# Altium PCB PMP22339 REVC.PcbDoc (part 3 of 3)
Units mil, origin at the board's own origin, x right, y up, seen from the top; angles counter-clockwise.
Board outline 4555 x 3750 mil, 4 copper layers (Top Layer, Signal Layer 2, Signal Layer 3, Bottom Layer), stack 62.6 mil thick; 180 components, 83 nets, 384 pads, 132 vias.
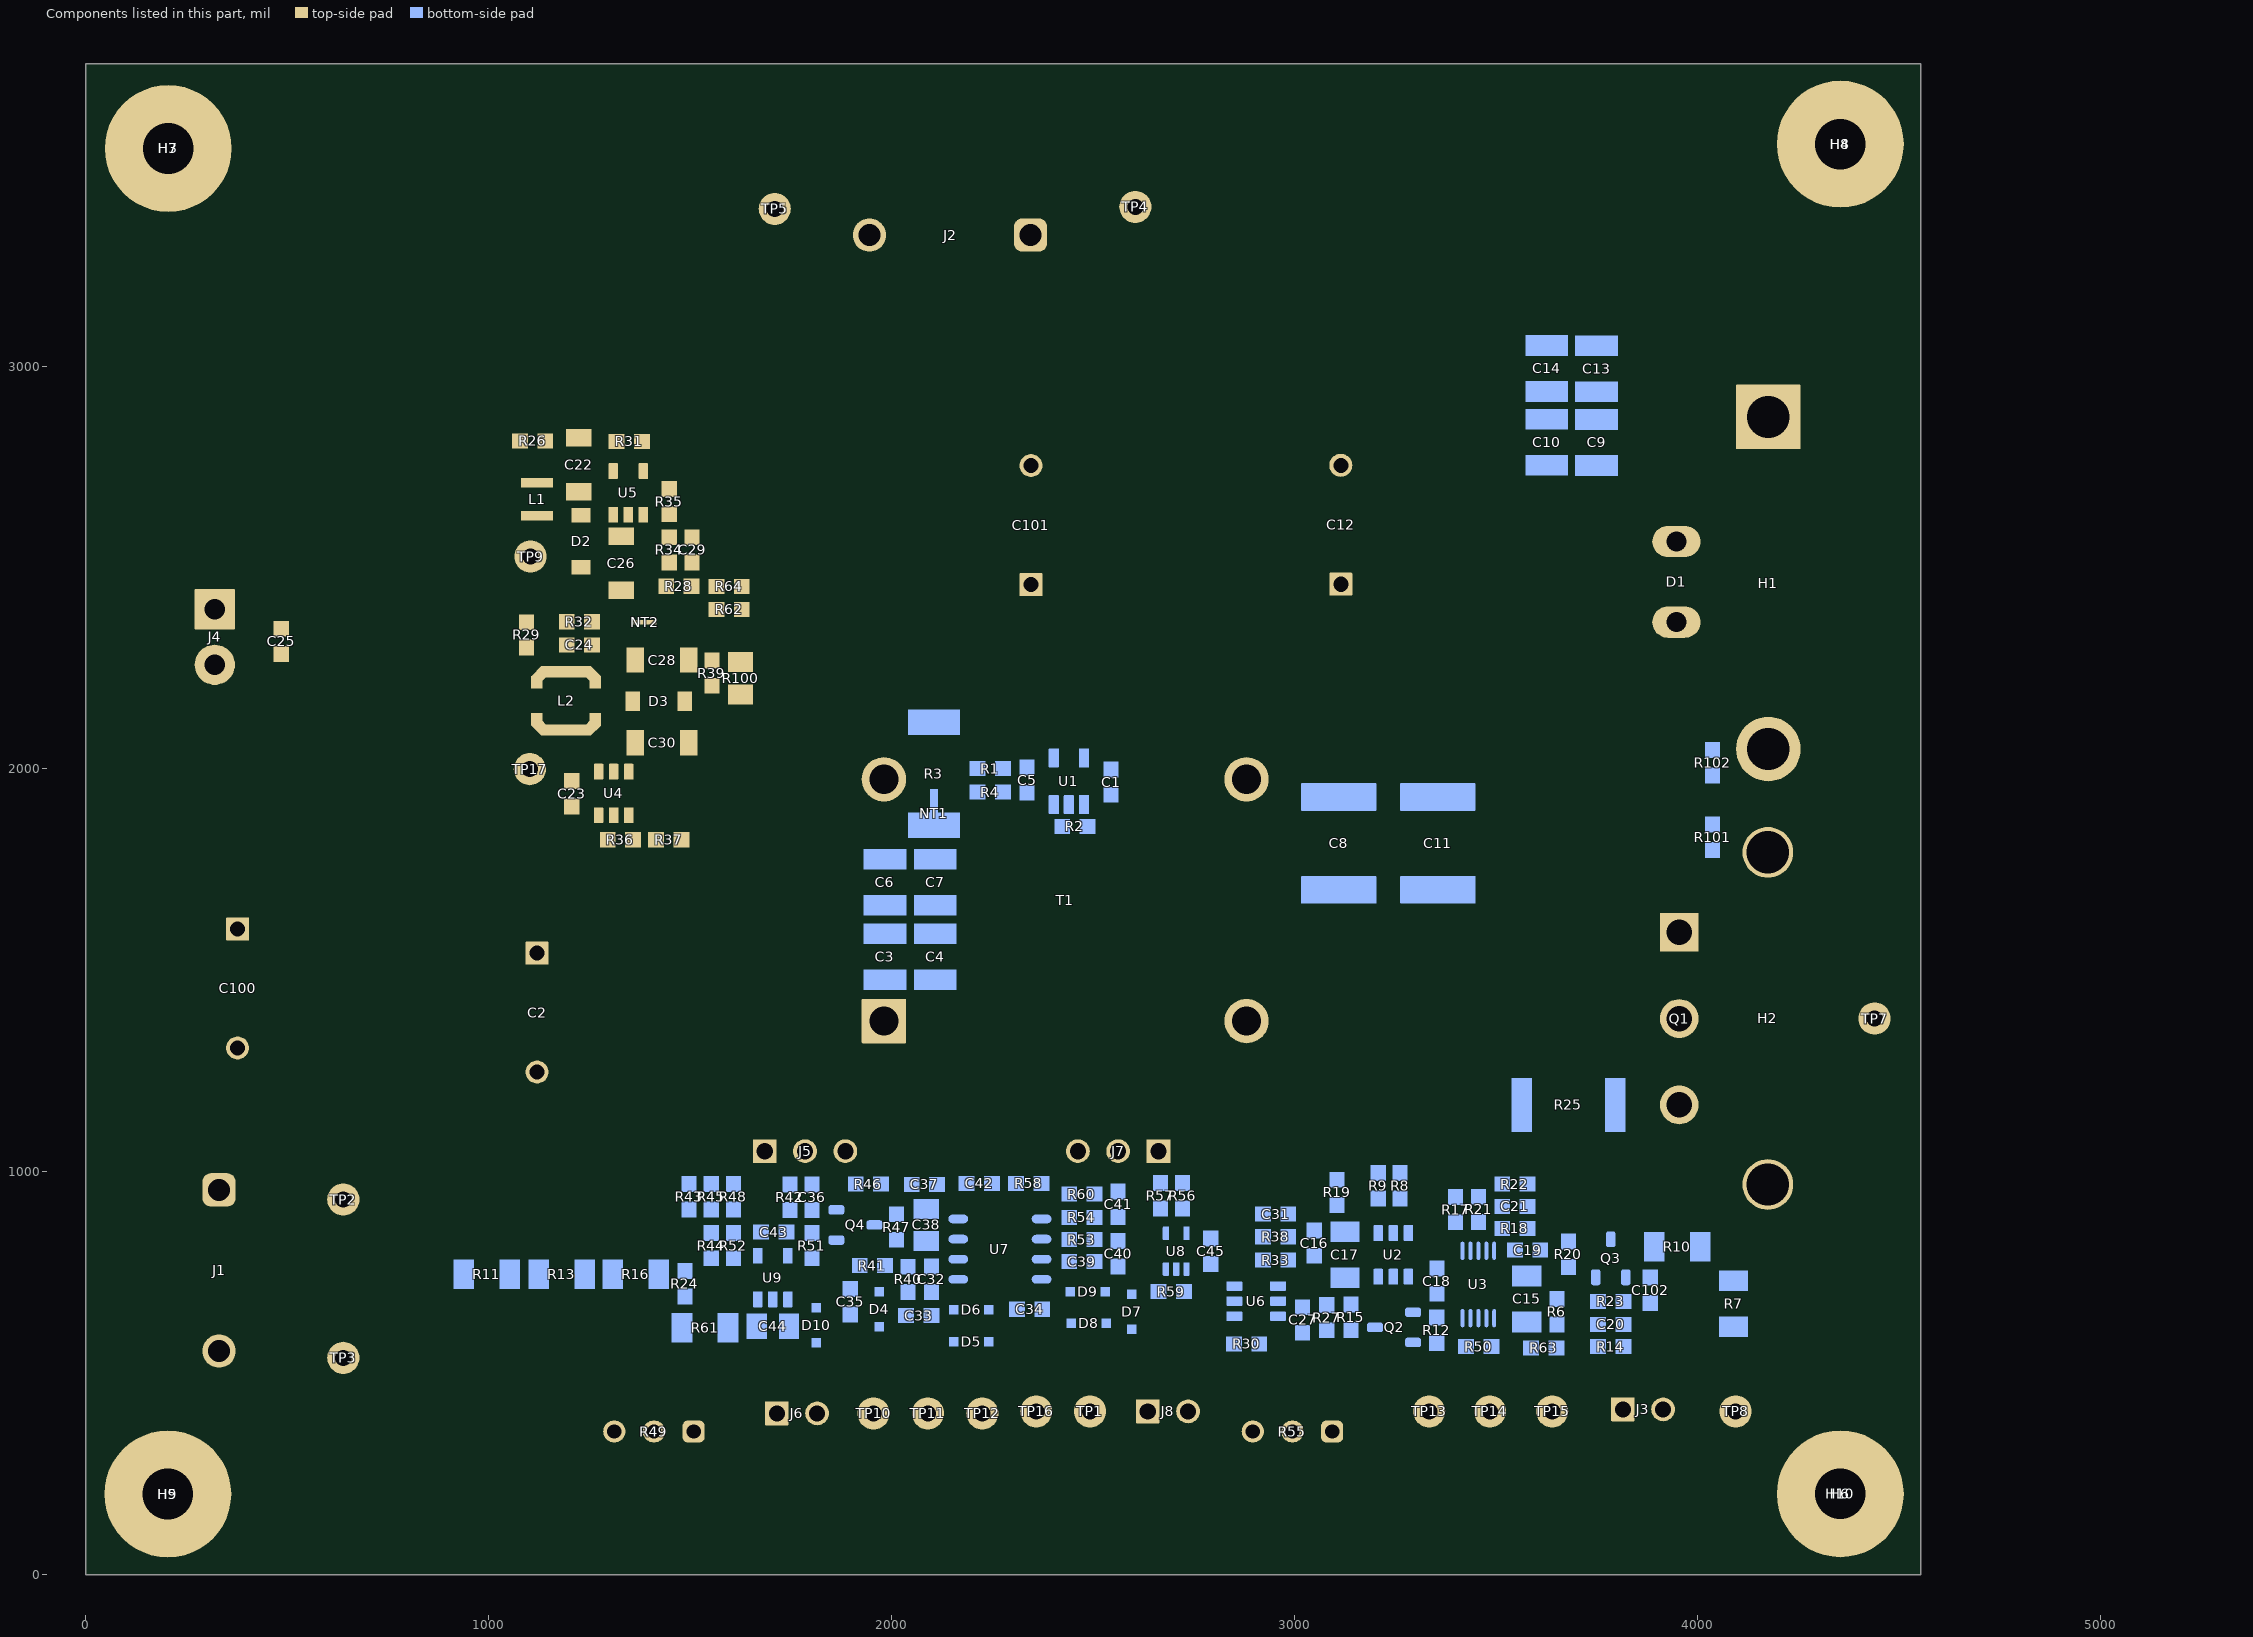
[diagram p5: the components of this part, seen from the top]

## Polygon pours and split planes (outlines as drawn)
VOUT on Bottom Layer "BOTTOM_LAYER_VOUT_P088" (solid, remove dead copper, pour order 88): 4042.91,2488.6 3318.01,2488.6 3226.61,2580 2276.8,2580 2160,2696.8 2160,3405 2250,3495 2440,3495 2520,3415 2520,2941.76 2561.76,2900 3472,2900 3565,2807 4038,2807 4050.01,2794.99 4050.01,2495.64
NetC8_2 on Bottom Layer "BOTTOM_LAYER_NETC8_2_P089" (solid, remove dead copper, pour order 89): 2775.5,1928.5 2836,1868 2836,1867 3704.57,1867 4064.88,2227.3 4064.88,2440 3318.01,2440 3230.66,2352.65 2833.65,2352.65 2776,2295
NetQ1_3 on Bottom Layer "BOTTOM_LAYER_NETQ1_3_P090" (solid, remove dead copper, pour order 90): 3770,1231.72 3983.28,1231.72 4015,1200 4015,1135.54 3979.46,1100 3770.17,1100 3770,1099.83
NetC8_1 on Bottom Layer "BOTTOM_LAYER_NETC8_1_P091" (solid, remove dead copper, pour order 91): 2814,1273 2776,1311 2776,1724 2837,1785 3706,1785 3825,1666 3825,1534.34 3891.34,1468 4477,1468 4517,1428 4517,1337 4472,1292 3261,1292 3242,1273
NetR1_1 on Bottom Layer "BOTTOM_LAYER_NETR1_1_P093" (solid, remove dead copper, pour order 93): 2235,2082.2 2235,2161.3 2188.88,2207.42 1947.42,2207.42 1904,2164 1904,1961.12 1935.12,1930 2010.16,1930 2040.16,1960 2040.16,2025.16 2058.05,2043.05 2195.84,2043.05
VIN on Bottom Layer "BOTTOM_LAYER_VIN_P094" (solid, remove dead copper, pour order 94): 1916,1514 1878,1476 1878,1303 1895,1286 2186.87,1286 2204.51,1303.64 2204.51,1472.06 2161.57,1515
-5V on Bottom Layer "BOTTOM_LAYER_-5V_P128" (solid, remove dead copper, pour order 128): 3214.7,849.62 3214.7,831.58 3224.71,821.56 3301.76,821.56 3302.32,822.12 3308.48,815.96 3308.48,771.29 3301.83,764.64 3190.83,764.64 3165,790.48 3165,849.31
GND on Bottom Layer "BOTTOM_LAYER_GND_P148" (solid, remove dead copper, pour order 148): 25.49,25.49 25.49,3724.51 4529.51,3724.51 4529.51,25.49
NetC9_2 on Bottom Layer "BOTTOM_LAYER_NETC9_2_P142" (solid, remove dead copper, pour order 142): 3697,2960.97 3697.03,2961 3803.27,2961 3803.27,2843 3696.97,2843
NetC10_2 on Bottom Layer "BOTTOM_LAYER_NETC10_2_P140" (solid, remove dead copper, pour order 140): 3573,2843 3573,2960.97 3572.97,2961 3573.97,2962 3678,2962 3678,2844 3679,2843
VOUT on Bottom Layer "BOTTOM_LAYER_VOUT_P138" (solid, remove dead copper, pour order 138): 4425,2857.42
NetC4_2 on Bottom Layer "BOTTOM_LAYER_NETC4_2_P136" (solid, remove dead copper, pour order 136): 2256,1674
NetC4_2 on Bottom Layer "BOTTOM_LAYER_NETC4_2_P134" (solid, remove dead copper, pour order 134): 2055,1687 2055,1566 2161.57,1566 2161.57,1686
NetC3_2 on Bottom Layer "BOTTOM_LAYER_NETC3_2_P130" (solid, remove dead copper, pour order 130): 1929,1690 2035.57,1690 2036.57,1689 2036.57,1564 1929,1564
-5V on Bottom Layer "BOTTOM_LAYER_-5V_P127" (solid, remove dead copper, pour order 127): 3040,545.6
-5V on Bottom Layer "BOTTOM_LAYER_-5V_P126" (solid, remove dead copper, pour order 126): 2971,728 2970.52,727.52 2909.87,727.52 2872.35,690 2859,690 2859,667.63 2873.03,667.63 2881,659.66 2881,617.81 2893.64,605.18 2962.82,605.18 2990.98,577.02 3039,577.02 3039,603.74 3019.34,613.17 2980,652.5 2979.5,652 2937.66,652 2930,659.66 2931,660.66 2931,693.18 2942,704.17 2952,704.17
+18V on Bottom Layer "BOTTOM_LAYER_+18V_P121" (solid, remove dead copper, pour order 121): 2861,818
+18V on Bottom Layer "BOTTOM_LAYER_+18V_P120" (solid, remove dead copper, pour order 120): 3030.46,811 3020.62,801.16 2965.91,801 2965.12,801.79 2965.12,758.1 3022.22,701 3049,701 3093.54,656.46 3093.54,681.67 3120.87,709 3207,709 3221,723 3221,754.74 3213.58,762.16 3092.36,762.16 3079,775.52 3079,798 3066,811
-5V on Bottom Layer "BOTTOM_LAYER_-5V_P119" (solid, remove dead copper, pour order 119): 3218,865.4 3188.4,895 3174.52,908.88 3174.52,917.58 3151.65,940.45 2976.45,940.45 2965,929 2965,820 3086,820 3095,811 3095,784 3106,773 3207,773 3218,784.1
NetC24_2 on Bottom Layer "BOTTOM_LAYER_NETC24_2_P106" (solid, remove dead copper, pour order 106): 1330.12,2035 1330.12,2211.19 1216.3,2325 1132,2325 1121.97,2314.97 1121.97,2222.03 1231,2113 1231,2059.4 1265.4,2025 1320.33,2025
NetC15_1 on Bottom Layer "BOTTOM_LAYER_NETC15_1_P098" (solid, remove dead copper, pour order 98): 3558.12,581.18
NetC15_1 on Bottom Layer "BOTTOM_LAYER_NETC15_1_P097" (solid, remove dead copper, pour order 97): 3499.81,661.21 3490.81,652.21 3490.81,618.49 3507.12,602.18 3613.12,602.18 3613.12,652.33 3605.12,660.33
NetR1_1 on Top Layer "TOP_LAYER_NETR1_1_P092" (solid, remove dead copper, pour order 92): 1904,2164 1947.42,2207.42 2188.88,2207.42 2235,2161.3 2235,2080 2198.05,2043.05 2058.05,2043.05 2040.16,2025.16 2040.16,1960 2010.16,1930 1935.12,1930 1904,1961.12
VIN on Top Layer "TOP_LAYER_VIN_P095" (solid, remove dead copper, pour order 95): 224,935 225,936 225,1331 303,1409 1547,1409 1549,1411 1809,1411 1811,1409 1916,1514 2176,1514 2280,1410 2280,1217.94 2247.06,1185 900,1185 735,1020 735,895 665,825 290,825 225,890
no net on Top Layer "TOP_LAYER_NONET_P096" (solid, remove dead copper, pour order 96): 216,1108
GND on Top Layer "TOP_LAYER_GND_P152" (solid, remove dead copper, pour order 152): 25.49,25.49 25.49,3724.51 4529.51,3724.51 4529.51,25.49
NetR1_1 on Top Layer "TOP_LAYER_NETR1_1_P150" (solid, remove dead copper, pour order 150): 2015,2173
GND on Top Layer "TOP_LAYER_GND_P112" (solid, remove dead copper, pour order 112): 1564,2531
GND on Top Layer "TOP_LAYER_GND_P111" (solid, remove dead copper, pour order 111): 1297,2599 1298,2598 1406,2598 1418,2586 1418,2550 1410,2542 1304,2542 1297,2549
GND on Top Layer "TOP_LAYER_GND_P110" (solid, remove dead copper, pour order 110): 1569,2671
GND on Top Layer "TOP_LAYER_GND_P108" (solid, remove dead copper, pour order 108): 1467,2716 1418,2716 1407,2705 1251.02,2705 1249.02,2707 1192,2707 1172,2687 1040,2687 1043.08,2683.92 1043.08,2658 1464.84,2658 1466.84,2660
NetC28_2 on Top Layer "TOP_LAYER_NETC28_2_P105" (solid, remove dead copper, pour order 105): 1328,1965.18 1292.7,1965.18 1275.53,1948 1276,1947.53 1276,1927.42 1348.17,1855.25 1438.25,1855.25 1519,1936 1519,2301 1516,2304 1413.78,2304 1403.78,2294 1403.78,2189 1404,2031.4 1419.6,2015.8 1419.6,1978.6 1406,1965
GND on Top Layer "TOP_LAYER_GND_P104" (solid, remove dead copper, pour order 104): 1098,2256 1103,2261 1208.12,2261 1236,2288.88 1236,2326 1236.28,2326.28 1376.72,2326.28 1386,2317 1386,2228 1371,2213 1304,2213 1289,2198 1098,2198
NetC24_2 on Top Layer "TOP_LAYER_NETC24_2_P103" (solid, remove dead copper, pour order 103): 1301.61,1995.49 1299,1998.11 1299,2051.7 1342.75,2095.45 1342.75,2096.34 1385,2096.34 1385,2026.63 1380.94,2022.58 1338.58,2022.58 1325,2009 1325,1977.85 1318.54,1971.4 1301.61,1971.4
NetC23_1 on Top Layer "TOP_LAYER_NETC23_1_P102" (solid, remove dead copper, pour order 102): 1285,1979 1285,2059 1342.75,2116.75 1364.75,2116.75 1376,2128 1376,2180.19 1363.19,2193 1299,2193 1281,2175 1078,2175 1062,2159 1062,1974 1087,1949 1254.97,1949 1255.97,1948
NetC26_1 on Top Layer "TOP_LAYER_NETC26_1_P101" (solid, remove dead copper, pour order 101): 1459,2519 1445,2533 1218,2533 1203,2518 1203,2474.47 1256.47,2421 1446,2421 1459,2434
NetC22_1 on Top Layer "TOP_LAYER_NETC22_1_P100" (solid, remove dead copper, pour order 100): 1340,2837 1332,2845 1129.92,2845 1118,2833.08 1118,2799 1080.72,2761.72 1080.72,2730.25 1080.74,2696.8 1159.44,2696.8 1185.01,2722.37 1268.63,2722.37 1274,2717 1274.85,2717.85 1320.85,2717.85 1340,2737
NetD2_2 on Top Layer "TOP_LAYER_NETD2_2_P099" (solid, remove dead copper, pour order 99): 1317.34,2652.16 1316,2653.51 1090.51,2653.51 1056,2619 1056,2518 1087,2487 1124,2487 1188,2551 1253.34,2551 1312.34,2610 1317.34,2615
GND on Signal Layer 2 "SIGNAL_LAYER_2_GND_P144" (solid, remove dead copper, pour order 144): 0,0 0,6875 5140,6875 5140,0
GND on Signal Layer 3 "SIGNAL_LAYER_3_GND_P146" (solid, remove dead copper, pour order 146): 0,0 0,6875 5140,6875 5140,0

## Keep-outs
Keep-Out Layer:
  text ".Layer_Name" at 577,-858.49 h60

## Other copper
Top Layer:
  pour cut-out: 2645,1240 2646.42,1241.42 2646.42,1252.1 2296.45,1252.1 2289.34,1245 2291.51,1242.83 2291.51,1235 2648.7,1235
  pour cut-out: 3570.97,1039 3594.97,1015 3609.27,1015 3609.27,1007.1 3608.74,1006.58 3608.15,1007.18 3584.84,1007.18 3562.02,1030
  pour cut-out: 3599,1017.87 4118.2,1017.87 4106.91,1006.58 3593.74,1006.58
  pour cut-out: 3571.97,1038 3570.97,1039 3286.24,1039 3286.24,1034.02 3279.22,1027 3570.55,1027
  pour cut-out: 5263,1135
  pour cut-out: 2646.42,1252.1 2810.3,1088.23 3261.18,1088.23 3261.18,1074.02 3260.2,1075 2799,1075 2634,1240
  text ".Layer_Name" at 577,-858.49 h60
Signal Layer 2:
  pour cut-out: 2736.54,1260 2492.22,1260 2490.22,1262 2487.14,1258.92 2487.14,1242.71 2741.98,1242.71
  pour cut-out: 3261.18,1088.23 3079.77,1088.23 3063,1105 2895,1105 2738.16,1261.84 2726.37,1250.05 2888.19,1088.23 3053.77,1088.23 3070,1072 3249.12,1072
Bottom Layer:
  pour cut-out: 1346.39,801.59 1377.56,801.59 1384.63,808.66 1390.68,802.6 1390.68,688.88 1390.56,688.76 1345,688.76
  pour cut-out: 1160,801.59 1199.49,801.59 1200,801.08 1200,688.76 1161.24,688.76 1160,690
  pour cut-out: 975,801.59 1015,801.59 1015,688.76 976.52,688.76
  pour cut-out: 4033.58,690.5 4145.52,690.5 4147.5,692.48 4156.42,683.56 4156.42,660.94 4165,652.36 4165,642.82 4141.78,642.82 4134.59,650 4034.92,650 4033.84,651.09
  pour cut-out: 3930,756.86 3930,871.31 3969.73,871.31 3970,871.57 3970,757.19
  pour cut-out: 1908.61,1525 2182,1525 2182,1553.57 2171.57,1564 1908.61,1564
  pour cut-out: 2819,1792 2820,1793 3729.82,1793 3729.82,1861 2819,1861
  pour cut-out: 3611,931 3650,931 3712,869 3712,824.11 3718.11,824.11 3732,838 3732,876.37 3657.9,950.47 3610.77,950.47 3610.24,951
  pour cut-out: 3284.8,1055 3696.36,1055 3696.36,1045 3290.8,1045
  pour cut-out: 3185.12,1037.66 2991.34,1037.66 3013,1016 3013,1005 3174.91,1005 3178.07,1008.16
  text ".Layer_Name" at 577,-858.49 h60

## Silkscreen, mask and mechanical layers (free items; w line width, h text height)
Top Overlay:
  lines w8: 1221.81,1832.06 1250,1855.25 ; 1403.89,2741.04 1403.89,2741.32 1443.57,2781 ; 1586.01,2816 1486.01,2716 ; 1684,1133 1782,1133 ; 2564,1133 2662,1133 ; 3870.12,888.05 3870.12,1872.3 ; 3870.12,1970.18 3870.12,2954.51 ; 1486,2716 1486.01,2716 ; 2087.79,1257.51 2087.8,1257.49
  text "DANGER HIGH VOLTAGE" at 3650.5,3665.3 h100 r180
  text "GND" at 2000,3655 h72.83 r180
  text "VOUT" at 2420,3655 h72.83 r180
  text "'.PRJ_Number'.PCB_Rev" at 745,3495 h108.27
  text "+" at 3195,2982.46 h72.83
  text "+" at 2433.75,2978.73 h72.83
  text "12V" at 55.89,2475 h72.83 r270
  text "GND" at 56.7,2326 h72.83 r270
  text "DANGER HIGH VOLTAGE" at 710,1225 h100 r270
  text "+" at 663.17,1088.73 h72.83
  text "+" at 1331.53,1014 h72.83
  text "VIN" at 45,980 h72.83 r270
  text "GND" at 50,630 h72.83 r270
  text "MB" at 2446,176.6 h72.83
  text "CHG" at 1695.23,176.26 h72.83
  text "CHG" at 2625.67,173 h72.83
  text "VSET" at 1698.36,120.26 h72.83
  text "CHG" at 2423,119 h72.83
  text "ISET" at 2628.8,117 h72.83
  text "/ENABLE" at 3733,106 h72.83
  text "Loop2" at 3507,65 h72.83 r90
  text "DAC" at 1698.36,64.26 h72.83
  text "ISET" at 2949.07,64 h72.83
  text "VSET" at 1333,63 h72.83
  text "ISNS" at 2424.03,63 h72.83
  text "Loop1" at 3353.16,63 h72.83 r90
  text "GND" at 3656.3,63 h72.83 r90
  text "GND" at 2248,61 h72.83 r90
  text "DAC" at 2628.8,61 h72.83
  text "GND" at 4117.3,60.57 h72.83 r90
  text "VREF1" at 1980,58 h72.83 r90
  text "VREF2" at 2113,58 h72.83 r90
  text "VREF3" at 2384,58 h72.83 r90
  text ".Layer_Name" at 577,-858.49 h60
Bottom Overlay:
  lines w8: 1553.3,1076.67 1604,1025.97 1604,1011 ; 3112,560 3112,539 3171,480 3171,479 ; 3295.52,878 3295.52,879.09 3311.38,894.96 3311.38,895.47 ; 3548.24,1007.18 3548.24,1034.24 3580,1066 3611,1066 ; 3573,362.54 3573,513.54 ; 3716.22,866.24 3781.31,916.01
  text ".Layer_Name" at 577,-858.49 h60
Top Paste:
  text ".Layer_Name" at 577,-858.49 h60
Bottom Paste:
  text ".Layer_Name" at 577,-858.49 h60
Top Solder:
  text ".Layer_Name" at 577,-858.49 h60
  text ".Layer_Name" at 577,-858.49 h60
Bottom Solder:
  text ".Layer_Name" at 577,-858.49 h60
Drill Guide:
  text ".Layer_Name" at 577,-858.49 h60
M1 Board Outline:
  the board outline again, w10
  text ".Layer_Name" at 577,-858.49 h60
M2 Board Dimensions:
  rectangle: 0,-275 125,-150
  rectangle: 125,-400 500,-275
  lines w7: 0,-275 1000,-275 ; 125,-400 125,-150 ; 250,-400 250,-150 ; 500,-400 500,-150 ; 750,-400 750,-150 ; 0,-400 1000,-400 1000,-150 0,-150 0,-400
  text ".Layer_Name" at 577,-858.49 h60
M3 3D STEP Top:
  text ".Layer_Name" at 577,-858.49 h60
M4 3D STEP Bottom:
  text ".Layer_Name" at 577,-858.49 h60
M5 Assembly Top:
  lines w10: -292,-930.17 6308,-930.17 ; -292,-726.83 6310,-726.83 ; -292,-523.5 -292,-1133.5 3713,-1133.5 6310,-1133.5 6310,-523.5 -291.5,-523.5 -291.5,-1133.5 1284,-1133.5 ; 2173,-1133.5 2173,-523.5 ; 3440,-726.83 3440,-523.5 ; 4280,-726.83 4280,-523.5 ; 4902,-1140 4902,-937.17
  text "PMP22339C" at 740,3495 h110
  text "COMPONENTS MARKED 'DNP' SHOULD NOT BE POPULATED." at 1153.5,-318.5 h60
  text "ASSEMBLY VARIANT:" at 1153,-434 h60
  text ".VariantName" at 2189,-434 h60
  text "PCB VIEWED FROM TOP SIDE" at -228.5,-655.67 h60
  text "BOARD #:" at 2248,-655.67 h60
  text ".PRJ_Number" at 2793.5,-655.67 h60
  text "REV:" at 3638,-655.67 h60
  text ".PCB_Rev" at 3929.5,-655.67 h60
  text "SVN REV:" at 4476,-655.67 h60
  text ".VersionControl_RevNumber" at 4982,-655.67 h60
  text "TID #:" at 2248,-859 h60
  text ".TID" at 2793.5,-859 h60
  text "PLOT NAME =" at -228.5,-1064.34 h60
  text ".plot_File_Name" at 577,-1064.34 h60
  text "GENERATED    :" at 2250,-1064.34 h60
  text ".Print_Date" at 3119.5,-1064.34 h60
  text ".Print_Time" at 3848.5,-1064.34 h60
  text "TEXAS INSTRUMENTS" at 5113,-1064.34 h60
M6 Assembly Bottom:
  lines w10: -292.5,-727.33 6309.5,-727.33 ; -290.5,-930.67 6309.5,-930.67 ; 1115.5,-1140.5 1115.5,-937.67 ; 1737.5,-727.33 1737.5,-524 ; 2577.5,-727.33 2577.5,-524 ; 3844.5,-1134 3844.5,-524 ; 4733.5,-1134 6309,-1134 6309,-524 -292.5,-524 -292.5,-1134 2304.5,-1134 6309.5,-1134 6309.5,-524
  text "COMPONENTS MARKED 'DNP' SHOULD NOT BE POPULATED." at 6102,-318 h60
  text ".VariantName" at 5058,-434 h60
  text "ASSEMBLY VARIANT:" at 6097,-434 h60
  text ".VersionControl_RevNumber" at 1035.5,-656.17 h60
  text "SVN REV:" at 1541.5,-656.17 h60
  text ".PCB_Rev" at 2088,-656.17 h60
  text "REV:" at 2379.5,-656.17 h60
  text ".PRJ_Number" at 3224,-656.17 h60
  text "BOARD #:" at 3769.5,-656.17 h60
  text "PCB VIEWED FROM BOTTOM SIDE" at 6246,-656.17 h60
  text ".TID" at 3224,-859.5 h60
  text "TID #:" at 3769.5,-859.5 h60
  text "TEXAS INSTRUMENTS" at 904.5,-1064.84 h60
  text ".Print_Time" at 2169,-1064.84 h60
  text ".Print_Date" at 2898,-1064.84 h60
  text "GENERATED    :" at 3767.5,-1064.84 h60
  text ".plot_File_Name" at 5440.5,-1064.84 h60
  text "PLOT NAME =" at 6246,-1064.84 h60
M9 Title Sheet:
  drawing of 57 lines, arcs and shapes, not listed
  text "1" at 739.84,8036.5 h70
  text "2" at 3235.5,8036.5 h70
  text "3" at 5724.84,8036.5 h70
  text "4" at 8231.51,8036.5 h70
  text "5" at 10730.5,8036.5 h70
  text "6" at 13235.5,8036.5 h70
  text "A" at -416.5,6893.5 h70
  text "A" at 14383.5,6893.5 h70
  text "B" at -416.5,4513.5 h70
  text "B" at 14383.5,4513.5 h70
  text "C" at -416.5,2138.5 h70
  text "C" at 14383.5,2138.5 h70
  text "PROJECT TITLE:" at 11343.5,277.5 h45
  text ".PRJ_Title" at 11393.5,144.17 h70
  text "DESIGNED FOR:" at 11343.5,-23.5 h45
  text ".PRJ_Customer" at 11393.5,-163.5 h70
  text "D" at -416.5,-231.5 h70
  text "D" at 14383.5,-231.5 h70
  text "FILE NAME:" at 11343.5,-323.5 h45
  text ".PCB_File_Name_No_Path" at 11393.5,-443.5 h70
  text "Texas Instruments (TI) and/or its licensors do not warrant the accuracy or completeness of this specification" at 6374,-605.34 h45
  text "ENGINEER:" at 11343.5,-613.5 h45
  text "LAYOUT BY:" at 12848.5,-613.5 h45
  text "or any information contained therein. TI and/or its licensors do not warrant that this design will meet" at 6329.01,-718 h45
  text ".PRJ_Engineer" at 11393.5,-768.49 h70
  text ".PCB_Layout" at 12899,-768.49 h70
  text "the specifications, will be suitable for your application or fit for any particular purpose, or will operate in" at 6329.01,-830.67 h45
  text ".Layer_Name" at 577,-858.49 h60
  text "ALTIUM DESIGNER VERSION:" at 12848.5,-923.5 h45
  text "an implementation. TI and/or its licensors do not warrant that the design is production worthy. You should" at 6329.01,-943.33 h45
  text "completely validate and test your design implementation to confirm the system functionality for your application." at 6374,-1056 h45
  text ".print_Scale" at 11393.5,-1056.83 h70
  text ".Application_BuildNumber" at 12899,-1056.83 h70
  text "1" at 739.84,-1263.5 h70
  text "2" at 3235.5,-1263.5 h70
  text "3" at 5724.84,-1263.5 h70
  text "4" at 8231.51,-1263.5 h70
  text "5" at 10730.5,-1263.5 h70
  text "6" at 13235.5,-1263.5 h70
M10 Fab Notes:
  drawing of 189 lines, arcs and shapes, not listed
  text "DESIGN INFORMATION" at 12382.02,6356.17 h60
  text "MIN. TRACK WIDTH:" at 11737.46,6224.05 h60
  text "8" at 12833.7,6224.05 h60
  text "MIL" at 12988.46,6224.05 h60
  text "MIN. CLEARANCE:" at 11737.46,6099.92 h60
  text "0.2" at 12773.7,6099.93 h60
  text "mm" at 12988.46,6099.92 h60
  text "MIN. VIA PAD SIZE:" at 11737.46,5975.8 h60
  text "24" at 12803.71,5975.8 h60
  text "MIL" at 12988.46,5975.8 h60
  text "0.05mm (2MIL)" at 12432.46,5845.9 h60
  text "MINIMUM ANNULAR RING" at 11408.23,5837.67 h60
  text "EXTERNAL" at 13140.46,5837.67 h60
  text "PER" at 11608.23,5727.55 h60
  text "IPC-D-275 CLASS 2 LEVEL C" at 11828.23,5727.54 h60
  text "MIL, HOLES" at 13316.46,5627.07 h60
  text "+/-" at 12924,5618.48 h60
  text "+/-" at 13778,5618.48 h60
  text "REGISTRATION TOLERANCES:" at 11408.23,5617.42 h60
  text "METAL" at 12608,5617.42 h60
  text "5" at 13184.2,5617.42 h60
  text "3" at 14017.2,5617.42 h60
  text "MIL" at 14133.46,5617.42 h60
  text "HOLE SIZE TOLERANCE (UNLESS OTHERWISE SPECIFIED):" at 11408.23,5519.1 h60
  text "+/-" at 13778,5516.23 h60
  text "3" at 14017.2,5515.17 h60
  text "MIL" at 14133.46,5515.17 h60
  text "MATERIAL:" at 11333.46,5377.52 h60
  text "FR-4 High Tg" at 12319.9,5249 h60
  text "X" at 12175.46,5241.01 h60
  text "FR-408" at 11754.46,5236.49 h60
  text "OTHER" at 13242.46,5236.49 h60
  text "62 MIL (1.6mm) +/-10%" at 12074.56,5093.46 h60
  text "X" at 11954.46,5091.01 h60
  text "THICKNESS:" at 11408.23,5085.24 h60
  text "OTHER" at 13359.46,5085.24 h60
  text "TOLERANCE:" at 11408.23,4946.92 h60
  text "X" at 12256.46,4946.92 h60
  text "ANSI IPC-6012 TYPE 3 CLASS 2" at 12434.48,4946.92 h60
  text "OTHER +/-" at 12434.46,4802.73 h60
  text "BOW & TWIST:" at 11408.23,4657.54 h60
  text "X" at 12256.46,4657.54 h60
  text "ANSI IPC-6012 TYPE 3 CLASS 2" at 12434.48,4657.54 h60
  text "OTHER +/-" at 12434.46,4510.85 h60
  text "DRILLING:" at 11333.46,4380.23 h60
  text "NC_DRILL FILES" at 13094.46,4275.04 h60
  text "REFERENCE:" at 11408.23,4271.1 h60
  text "X" at 12065.46,4271.01 h60
  text "AS SHOWN" at 12243.46,4271.1 h60
  text "X" at 12966.46,4271.1 h60
  text "OTHER" at 13392.46,4128.85 h60
  text "PTH COPPER THICKNESS:" at 11407.91,4125.32 h60
  text "X" at 12547.14,4125.32 h60
  text "20-30 um" at 12675.14,4125.32 h60
  text "BOARD FINISH:" at 11333.46,3977.73 h60
  text "SILKSCREEN:" at 11488.68,3867.6 h60
  text "X" at 12446.46,3867.6 h60
  text "TOP" at 12563.46,3867.6 h60
  text "X" at 12956.46,3867.6 h60
  text "BOTTOM" at 13074.46,3867.6 h60
  text "SILKSCREEN COLOR:" at 11488.68,3712.41 h60
  text "X" at 12445.46,3712.41 h60
  text "WHITE" at 12563.46,3712.41 h60
  text "OTHER" at 13074.46,3712.41 h60
  text "X" at 12576.46,3568.96 h60
  text "GREEN" at 12694.46,3568.96 h60
  text "OTHER" at 13312.46,3568.96 h60
  text "SOLDER RESIST COLOR:" at 11488.68,3562.1 h60
  text "X" at 12576.46,3414.71 h60
  text "MATTE" at 12694.46,3414.71 h60
  text "SEMI-GLOSS" at 13312,3414.07 h60
  text "IMMERSION GOLD (ENIG)" at 12394.46,3241.94 h60
  text "ENEPIG" at 13732,3234.72 h60
  text "SURFACE FINISH:" at 11333.46,3233.72 h60
  text "X" at 12216.46,3233.72 h60
  text "IMM. TIN/SILVER OR EQUIV" at 11663,3096.4 h60
  text "OTHER" at 13094.46,3092.47 h60
  text "ARRAY/PANEL:" at 11333.46,2937.09 h60
  text "CUT AND TRIM PER M1 BOARD OUTLINE" at 12394.46,2928.87 h60
  text "N.C. ROUTE" at 12394.46,2792.9 h60
  text "X" at 13082.46,2792.9 h60
  text "V. SCORE" at 13260.46,2792.9 h60
  text "CERTIFICATION:" at 11333.46,2663.77 h60
  text "MATERIALS AND WORKMANSHIP FOR ALL PCBS" at 12058.46,2663.77 h60
  text "TO MEET OR EXCEED THE REQUIREMENTS OF:" at 12058.46,2569.71 h60
  text "X" at 11695.97,2441.08 h60
  text "ANSI IPC-A-600F CLASS ->" at 11823.96,2441.08 h60
  text "X" at 13471.97,2441.08 h60
  text "2" at 13581.96,2441.08 h60
  text "1" at 13266.96,2439.58 h60
  text "3" at 13935.96,2439.58 h60
  text "X" at 12507.97,2293.39 h60
  text "RoHS" at 12635.96,2293.39 h60
  text "OTHER" at 13280.36,2293.39 h60
  text "PER ORDER" at 13677.42,2293.39 h60
  text "ALL BOARDS MUST MEET OR EXCEED UL94-V0 REQUIREMENTS." at 11361,2139.57 h60
  text "PCB MUST BEAR THE UL94V-0 UL REGISTERED MATERIAL ID NUMBER" at 11361,2023.5 h60
  text "ADDITIONAL REQUIREMENTS:" at 11333.46,1854.08 h60
  text "MICROSECTION:" at 11408.23,1746.95 h60
  text "YES" at 12313.96,1746.95 h60
  text "REQUIRED" at 13175.46,1602.62 h60
  text "BARE BOARD ELEC. TEST:" at 11408.23,1599.76 h60
  text "NONE" at 12713.96,1599.76 h60
  text "X" at 13057.46,1599.76 h60
  text "PER ORDER" at 13767.46,1599.76 h60
  text "XX MIL VIAS REQUIRE NON-CONDUCTIVE FILL AND PLANARIZE" at 11576.38,1394.82 h59
  text "XX MIL VIAS REQUIRE CONDUCTIVE FILL AND PLANARIZE" at 11584.38,1290.84 h60
  text "OUTER XX MIL TRACES REQUIRE 50 OHM SINGLE-ENDED IMPEDANCE" at 11583.39,1127.46 h58
  text "LAYER 2 & 3 (INNER LAYERS) XX MIL WIDE, XX MIL SPACE / TRACES REQUIRE 100 OHM DIFFERENTIAL IMPEDANCE" at 11575.39,891.74 h60
  text ".Layer_Name" at 577,-858.49 h60
M11 Gerber Information:
  lines w10: -292,-930.17 6308,-930.17 ; -292,-726.83 6310,-726.83 ; -292,-523.5 -292,-1133.5 3713,-1133.5 6310,-1133.5 6310,-523.5 -291.5,-523.5 -291.5,-1133.5 1284,-1133.5 ; 2173,-1133.5 2173,-523.5 ; 3440,-726.83 3440,-523.5 ; 4280,-726.83 4280,-523.5 ; 4902,-1140 4902,-937.17
  text "ALL ARTWORK VIEWED FROM TOP SIDE" at -228.5,-655.67 h60
  text "BOARD #:" at 2248,-655.67 h60
  text ".PRJ_Number" at 2793.5,-655.67 h60
  text "REV:" at 3638,-655.67 h60
  text ".PCB_Rev" at 3929.5,-655.67 h60
  text "SVN REV:" at 4476,-655.67 h60
  text ".VersionControl_RevNumber" at 4982,-655.67 h60
  text "LAYER NAME =" at -228.5,-858.49 h60
  text "TID #:" at 2248,-859 h60
  text ".TID" at 2793.5,-859 h60
  text "PLOT NAME =" at -228.5,-1064.34 h60
  text ".plot_File_Name" at 577,-1064.34 h60
  text "GENERATED    :" at 2250,-1064.34 h60
  text ".Print_Date" at 3119.5,-1064.34 h60
  text ".Print_Time" at 3848.5,-1064.34 h60
  text "TEXAS INSTRUMENTS" at 5113,-1064.34 h60
M12 Stackup:
  drawing of 295 lines, arcs and shapes, not listed
  text "Layer" at 9780.58,7835 h60
  text "Name" at 10190.49,7835 h60
  text "Material" at 11130.23,7835 h60
  text "Thickness" at 11990,7835 h60
  text "Constant" at 12639.84,7835 h60
  text "Board Layer Stack" at 13209.7,7835 h60
  text "1" at 9780.58,7715 h60
  text "Top Overlay" at 10190.49,7715 h60
  text "2" at 9780.58,7595 h60
  text "Top Solder" at 10190.49,7595 h60
  text "Solder Resist" at 11130.23,7595 h60
  text "0.40mil" at 11990,7595 h60
  text "3.5" at 12639.84,7595 h60
  text "3" at 9780.58,7475 h60
  text "Top Layer" at 10190.49,7475 h60
  text "Copper" at 11130.23,7475 h60
  text "2.40mil" at 11990,7475 h60
  text "4" at 9780.58,7355 h60
  text "Dielectric1" at 10190.49,7355 h60
  text "FR-4" at 11130.23,7355 h60
  text "18.00mil" at 11990,7355 h60
  text "4.8" at 12639.84,7355 h60
  text "5" at 9780.58,7235 h60
  text "Signal Layer 2" at 10190.49,7235 h60
  text "Copper" at 11130.23,7235 h60
  text "2.40mil" at 11990,7235 h60
  text "6" at 9780.58,7115 h60
  text "Dielectric 2" at 10190.49,7115 h60
  text "17.00mil" at 11990,7115 h60
  text "4.2" at 12639.84,7115 h60
  text "7" at 9780.58,6995 h60
  text "Signal Layer 3" at 10190.49,6995 h60
  text "Copper" at 11130.23,6995 h60
  text "2.40mil" at 11990,6995 h60
  text "8" at 9780.58,6875 h60
  text "Dielectric 3" at 10190.49,6875 h60
  text "18.00mil" at 11990,6875 h60
  text "4.2" at 12639.84,6875 h60
  text "9" at 9780.58,6755 h60
  text "Bottom Layer" at 10190.49,6755 h60
  text "Copper" at 11130.23,6755 h60
  text "2.40mil" at 11990,6755 h60
  text "10" at 9780.58,6635 h60
  text "Bottom Solder" at 10190.49,6635 h60
  text "Solder Resist" at 11130.23,6635 h60
  text "0.40mil" at 11990,6635 h60
  text "3.5" at 12639.84,6635 h60
  text "11" at 9780.58,6515 h60
  text "Bottom Overlay" at 10190.49,6515 h60
  text ".Layer_Name" at 577,-858.49 h60
M13 Component Bodies Top:
  text ".Layer_Name" at 577,-858.49 h60
M14 Component Bodies Bottom:
  text ".Layer_Name" at 577,-858.49 h60
M15 Courtyards Top:
  text ".Layer_Name" at 577,-858.49 h60
M16 Courtyards Bottom:
  text ".Layer_Name" at 577,-858.49 h60
Drill Drawing:
  circle w10: c6258.72,3619.32 r16.58
  circle w10: c6258.72,3619.32 r27.63
  circle w10: c6258.72,2624.76 r27.63
  lines w10: 6231.09,2735.27 6244.9,2735.27 6244.9,2721.46 6272.53,2721.46 6272.53,2735.27 6286.34,2735.27 6286.34,2762.9 6272.53,2762.9 6272.53,2776.71 6244.9,2776.71 6244.9,2762.9 6231.09,2762.9 6231.09,2735.27 ; 6231.09,2901.03 6286.34,2901.03 6258.72,2845.78 6231.09,2901.03 ; 6231.09,2983.91 6244.9,2983.91 6258.72,2970.1 6272.53,2983.91 6286.34,2983.91 6272.53,2997.72 6286.34,3011.54 6272.53,3011.54 6258.72,3025.35 6244.9,3011.54 6231.09,3011.54 6244.9,2997.72 6231.09,2983.91 ; 6231.09,3218.74 6231.09,3232.55 6244.9,3246.36 6231.09,3260.18 6231.09,3273.99 6244.9,3273.99 6258.72,3260.18 6272.53,3273.99 6286.34,3273.99 6286.34,3260.18 6272.53,3246.36 6286.34,3232.55 6286.34,3218.74 6272.53,3218.74 6258.72,3232.55 6244.9,3218.74 6231.09,3218.74 ; 6231.09,3343.06 6286.34,3343.06 6286.34,3398.31 6231.09,3398.31 6231.09,3343.06 ; 6231.09,3467.38 6286.34,3467.38 6286.34,3522.63 6231.09,3522.63 6231.09,3467.38 ; 6231.09,3840.34 6231.09,3854.15 6244.9,3867.96 6231.09,3881.78 6231.09,3895.59 6244.9,3895.59 6258.72,3881.78 6272.53,3895.59 6286.34,3895.59 6286.34,3881.78 6272.53,3867.96 6286.34,3854.15 6286.34,3840.34 6272.53,3840.34 6258.72,3854.15 6244.9,3840.34 6231.09,3840.34 ; 6231.09,3978.47 6244.9,3978.47 6244.9,3964.66 6272.53,3964.66 6272.53,3978.47 6286.34,3978.47 6286.34,4006.1 6272.53,4006.1 6272.53,4019.91 6244.9,4019.91 6244.9,4006.1 6231.09,4006.1 6231.09,3978.47 ; 6242.14,2989.43 6250.43,2989.43 6258.72,2981.15 6267.01,2989.43 6275.29,2989.43 6267.01,2997.72 6275.29,3006.01 6267.01,3006.01 6258.72,3014.3 6250.43,3006.01 6242.14,3006.01 6250.43,2997.72 6242.14,2989.43 ; 6242.14,3478.43 6275.29,3478.43 6275.29,3511.58 6242.14,3511.58 6242.14,3478.43 ; 6242.14,3851.39 6242.14,3859.67 6250.43,3867.96 6242.14,3876.25 6242.14,3884.54 6250.43,3884.54 6258.72,3876.25 6267.01,3884.54 6275.29,3884.54 6275.29,3876.25 6267.01,3867.96 6275.29,3859.67 6275.29,3851.39 6267.01,3851.39 6258.72,3859.67 6250.43,3851.39 6242.14,3851.39 ; 6242.14,3983.99 6250.43,3983.99 6250.43,3975.71 6267.01,3975.71 6267.01,3983.99 6275.29,3983.99 6275.29,4000.57 6267.01,4000.57 6267.01,4008.86 6250.43,4008.86 6250.43,4000.57 6242.14,4000.57 6242.14,3983.99
  lines w12: 6181,2559.84 9412.49,2559.84 ; 6181,4051.68 9412.49,4051.68 ; 6518.86,2435.52 6518.86,4176 ; 6850.86,2435.52 6850.86,4176 ; 7487.43,2435.52 7487.43,4176 ; 7746.57,2435.52 7746.57,4176 ; 8121.72,2435.52 8121.72,4176 ; 8846.05,2435.52 8846.05,4176 ; 6181,2435.52 9412.49,2435.52 9412.49,4176 6181,4176 6181,2435.52
  text "Symbol" at 6255.59,4088.98 h72
  text "Quantity" at 6556.16,4088.98 h72
  text "Finished Hole Size" at 6888.16,4088.98 h72
  text "Plated" at 7524.72,4088.98 h72
  text "Hole Type" at 7783.86,4088.98 h72
  text "Drill Layer Pair" at 8159.02,4088.98 h72
  text "Hole Tolerance" at 8883.35,4088.98 h72
  text "21" at 6556.16,3964.66 h60
  text "10.00mil (0.254mm)" at 6888.16,3964.66 h60
  text "PTH" at 7524.72,3964.66 h60
  text "Round" at 7783.86,3964.66 h60
  text "Top Layer - Bottom Layer" at 8159.02,3964.66 h60
  text "110" at 6556.16,3840.34 h60
  text "16.00mil (0.406mm)" at 6888.16,3840.34 h60
  text "PTH" at 7524.72,3840.34 h60
  text "Round" at 7783.86,3840.34 h60
  text "Top Layer - Bottom Layer" at 8159.02,3840.34 h60
  text "1" at 6556.16,3716.02 h60
  text "34.00mil (0.864mm)" at 6888.16,3716.02 h60
  text "PTH" at 7524.72,3716.02 h60
  text "Round" at 7783.86,3716.02 h60
  text "Top Layer - Bottom Layer" at 8159.02,3716.02 h60
  text "A" at 6230.31,3706.02 h55.25
  text "6" at 6556.16,3591.7 h60
  text "35.43mil (0.900mm)" at 6888.16,3591.7 h60
  text "PTH" at 7524.72,3591.7 h60
  text "Round" at 7783.86,3591.7 h60
  text "Top Layer - Bottom Layer" at 8159.02,3591.7 h60
  text "8" at 6556.16,3467.38 h60
  text "37.40mil (0.950mm)" at 6888.16,3467.38 h60
  text "PTH" at 7524.72,3467.38 h60
  text "Round" at 7783.86,3467.38 h60
  text "Top Layer - Bottom Layer" at 8159.02,3467.38 h60
  text "28" at 6556.16,3343.06 h60
  text "40.00mil (1.016mm)" at 6888.16,3343.06 h60
  text "PTH" at 7524.72,3343.06 h60
  text "Round" at 7783.86,3343.06 h60
  text "Top Layer - Bottom Layer" at 8159.02,3343.06 h60
  text "4" at 6556.16,3218.74 h60
  text "50.00mil (1.270mm)" at 6888.16,3218.74 h60
  text "PTH" at 7524.72,3218.74 h60
  text "Round" at 7783.86,3218.74 h60
  text "Top Layer - Bottom Layer" at 8159.02,3218.74 h60
  text "4" at 6556.16,3094.42 h60
  text "55.12mil (1.400mm)" at 6888.16,3094.42 h60
  text "PTH" at 7524.72,3094.42 h60
  text "Round" at 7783.86,3094.42 h60
  text "Top Layer - Bottom Layer" at 8159.02,3094.42 h60
  text "+3.94mil/-0.00mil" at 8883.35,3094.42 h60
  text "C" at 6230.31,3084.43 h55.25
  text "3" at 6556.16,2970.1 h60
  text "62.99mil (1.600mm)" at 6888.16,2970.1 h60
  text "PTH" at 7524.72,2970.1 h60
  text "Round" at 7783.86,2970.1 h60
  text "Top Layer - Bottom Layer" at 8159.02,2970.1 h60
  text "4" at 6556.16,2845.78 h60
  text "72.84mil (1.850mm)" at 6888.16,2845.78 h60
  text "PTH" at 7524.72,2845.78 h60
  text "Round" at 7783.86,2845.78 h60
  text "Top Layer - Bottom Layer" at 8159.02,2845.78 h60
  text "4" at 6556.16,2721.46 h60
  text "105.12mil (2.670mm)" at 6888.16,2721.46 h60
  text "PTH" at 7524.72,2721.46 h60
  text "Round" at 7783.86,2721.46 h60
  text "Top Layer - Bottom Layer" at 8159.02,2721.46 h60
  text "4" at 6556.16,2597.14 h60
  text "125.98mil (3.200mm)" at 6888.16,2597.14 h60
  text "PTH" at 7524.72,2597.14 h60
  text "Round" at 7783.86,2597.14 h60
  text "Top Layer - Bottom Layer" at 8159.02,2597.14 h60
  text "197 Total" at 6556.16,2472.82 h60
  text ".Layer_Name" at 577,-858.49 h60
M17 Embedded Cavity:
  text ".Layer_Name" at 577,-858.49 h60
M18 Embedded Assembly:
  text ".Layer_Name" at 577,-858.49 h60
M19 Embedded Keepout:
  text ".Layer_Name" at 577,-858.49 h60

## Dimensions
0,0 to 0,3750 on M2 Board Dimensions
0,0 to 4555,1 on M2 Board Dimensions
0,-400 to 1000,-400 on M2 Board Dimensions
